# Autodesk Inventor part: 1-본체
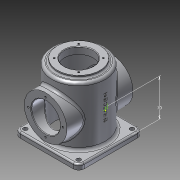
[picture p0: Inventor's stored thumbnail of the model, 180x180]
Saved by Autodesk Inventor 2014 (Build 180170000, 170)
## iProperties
Created: 2015-10
Part Number: 1-본체
Material: 알루미늄 6061
Document SubType Name: Modeling
Designer: Administrator
Mass: 989.425 g
Surface Area: 1040.74 cm^2
Volume: 365.101 cm^3
Density: 2.71 g/cm^3
Appearance: 알루미늄 - 평지
Author: Administrator
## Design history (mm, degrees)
sketch "스케치3"
  geometry: L1 (0, 55)-(-50, 55); L2 (-50, 55)-(-50, -55); L3 (-50, -55)-(0, -55); L4 (0, -55)-(0, 55); 2 further points
  constraints: 8 end point, 2 parallel, 1 coincident, 1 horizontal, 1 midpoint, 1 perpendicular
  dimensions: "d13" = 100 diameter of L2 L4; "d14" = 110 distance between parallel lines of L3 L1
revolve "회전2" sketch "스케치3" stored, may be unused: angle "d15" = 90 deg
sketch "스케치4"
  geometry: L1 (-60, -60)-(60, -60); L2 (60, -60)-(60, 60); L3 (60, 60)-(-60, 60); L4 (-60, 60)-(-60, -60); L5 (-60, -60)-(60, 60); L6 (60, -60)-(-60, 60); C1 r 50 at (0, 0) reference; 2 further points
  constraints: 12 end point, 2 midpoint, 2 parallel, 2 perpendicular, 1 horizontal, 1 horizontal alignment
  dimensions: "d16" = 120 distance of L3.end L1.start
extrude "돌출1" join sketch "스케치4" distance "d17" = 10; taper "d18" = 0 deg
sketch "스케치9"
  geometry: L1 (60, -65)-(-60, -65) reference; C1 r 40 at (0, -5); 2 further points
  constraints: 1 centre point, 1 midpoint, 1 vertical alignment
  dimensions: "d54" = 80 diameter of C1; "d55" = 60 distance from line of L1 C1.centre
extrude "돌출4" join sketch "스케치9" stored distance "d56" = 124; taper "d57" = 0 deg
node "작업 평면1"
sketch "스케치6"
  geometry: C1 r 40 at (0, 0); 1 further point
  constraints: 1 centre point, 1 coincident
  dimensions: "d32" = 80 diameter of C1
extrude "돌출3" join sketch "스케치6" stored distance "d33" = 124; taper "d34" = 0 deg
sketch "스케치7"
  geometry: L1 (0, 47)-(-45, 47); L2 (-45, 47)-(-45, -65); L3 (-45, -65)-(0, -65); L4 (0, -65)-(0, 47); L5 (60, -65)-(-60, -65) reference; L6 (0, -90)-(0, 85) reference; L7 (0, 47)-(-27, 47); L8 (-27, 47)-(-27, 60); L9 (-27, 60)-(0, 60); L10 (0, 60)-(0, 47); L11 (40, 60)-(-40, 60) reference; 1 further point
  constraints: 16 end point, 4 parallel, 3 collinear, 2 horizontal, 2 perpendicular
  dimensions: "d35" = 90 diameter of L2 L4; "d36" = 112 distance between parallel lines of L3 L1; "d37" = 13 distance between parallel lines of L1 L9 (derived); "d38" = 54 diameter of L8 L4
revolve "회전3" sketch "스케치7" stored, may be unused: angle "d39" = 90 deg
hole "구멍3" diameter "d60" = 54; stored, may be unused: countersink angle "d64" = 90 deg, drill point angle "d66" = 0 deg; dims "d58" = 10, "d59" = 10, "d61" = 8, "d62" = 90, "d63" = 112, "d65" = 10
fillet "모깎기2" dims "d67" = 3
sketch "스케치10"
  geometry: L1 (0, 0)-(0, 32.5)
  constraints: 2 end point, 1 vertical
  dimensions: "d68" = 32.5 distance of L1.start L1.end
hole "구멍4" sketch "스케치10" at (0, 32.5) diameter "d69" = 3.242; stored, may be unused: countersink angle "d73" = 90 deg, drill point angle "d75" = 118 deg; dims "d70" = 8, "d71" = 90, "d72" = 112, "d74" = 10
sketch "스케치11"
  geometry: L1 (0, 0)-(0, -32.5)
  constraints: 2 end point, 1 vertical
  dimensions: "d79" = 32.5 distance of L1.start L1.end
hole "구멍5" sketch "스케치11" at (0, -32.5) diameter "d80" = 3.242; stored, may be unused: countersink angle "d84" = 90 deg, drill point angle "d86" = 118 deg; dims "d81" = 8, "d82" = 90, "d83" = 112, "d85" = 10
sketch "스케치12" dims "d90" = 65
  geometry: L1 (0, 0)-(22.981, 22.981); L2 (-84, 0)-(84, 0) reference; 1 further point
  constraints: 2 end point, 1 coincident, 3 other
  dimensions: "d92" = 45 deg angle of L2 L1
hole "구멍6" sketch "스케치12" at (22.981, 22.981) diameter "d93" = 3.242; stored, may be unused: countersink angle "d97" = 90 deg, drill point angle "d99" = 118 deg; dims "d94" = 8, "d95" = 90, "d96" = 112, "d98" = 10
fillet "모깎기3" dims "d103" = 10
hole "구멍7" diameter "d106" = 8; stored, may be unused: countersink angle "d110" = 90 deg, drill point angle "d112" = 0 deg; dims "d104" = 10, "d105" = 10, "d107" = 8, "d108" = 90, "d109" = 112, "d111" = 10
hole "구멍8" diameter "d115" = 8; stored, may be unused: countersink angle "d119" = 90 deg, drill point angle "d121" = 0 deg; dims "d113" = 10, "d114" = 10, "d116" = 8, "d117" = 90, "d118" = 112, "d120" = 10
hole "구멍9" diameter "d124" = 8; stored, may be unused: countersink angle "d128" = 90 deg, drill point angle "d130" = 0 deg; dims "d122" = 10, "d123" = 10, "d125" = 8, "d126" = 90, "d127" = 112, "d129" = 10
hole "구멍10" diameter "d133" = 8; stored, may be unused: countersink angle "d137" = 90 deg, drill point angle "d139" = 0 deg; dims "d131" = 10, "d132" = 10, "d134" = 8, "d135" = 90, "d136" = 112, "d138" = 10
fillet "모깎기4" dims "d140" = 5
fillet "모깎기5" dims "d141" = 5
fillet "모깎기6" dims "d142" = 5
fillet "모깎기7" dims "d143" = 3
fillet "모깎기8" dims "d144" = 3
chamfer "모따기1" distance "d145" = 1; stored, may be unused: second distance "d146" = 2, angle "d147" = 45 deg
node "작업 평면2"
sketch "스케치14"
  geometry: L1 (-3.602, 1.398)-(-3.602, 8.602); L2 (-3.602, 8.602)-(3.602, 8.602); L3 (3.602, 8.602)-(3.602, 1.398); L4 (3.602, 1.398)-(-3.602, 1.398); L5 (50, -65)-(-50, -65) reference; 3 further points
  constraints: 2 midpoint, 1 perpendicular, 1 vertical, 1 vertical alignment, 2 other
  dimensions: "d148" = 70 distance from line of L5 point (3.602, 5)
node "솔리드2"
pattern_circular "원형 패턴2" dims angle "d77" = 360 deg
pattern_circular "원형 패턴3" dims angle "d88" = 360 deg
pattern_circular "원형 패턴4" dims angle "d101" = 360 deg
node "투영된 루프1"
other parameters: "d31" = -125
